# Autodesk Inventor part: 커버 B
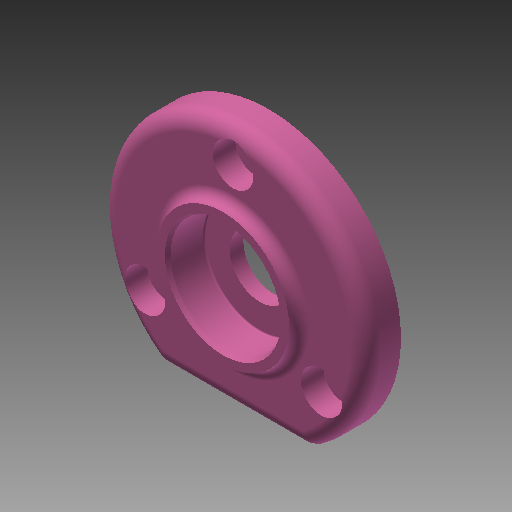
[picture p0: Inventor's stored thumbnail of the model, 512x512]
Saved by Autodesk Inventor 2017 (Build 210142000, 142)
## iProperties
Created: 2020-04
Part Number: 커버 B
Material: 알루미늄 6061
Document SubType Name: Modeling
Designer: mduedu
Density: 2.71 g/cm^3
Appearance: 분홍색
Mass: 33.6764 g
Surface Area: 62.2842 cm^2
Volume: 12.4267 cm^3
Author: mduedu
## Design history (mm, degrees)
sketch "스케치1"
  geometry: C1 r 26 at (0, 0); 1 further point
  constraints: 1 centre point, 1 coincident
  dimensions: "d0" = 52 diameter of C1
extrude "돌출1" new body sketch "스케치1" distance "d1" = 7; taper "d2" = 0 deg
sketch "스케치2"
  geometry: L1 (-14.62, -21.5)-(14.62, -21.5); A1 r 26 centre (0, 0) between (-14.62, -21.5) and (14.62, -21.5) reference; 1 further point
  constraints: 2 end point, 2 point on circle, 1 horizontal
  dimensions: "d3" = 21.5 distance from line of L1 point (0, 0)
extrude "돌출2" cut sketch "스케치2" stored distance "d4" = 7; taper "d5" = 0 deg
sketch "스케치6"
  geometry: C1 r 13 at (0, 0); 1 further point
  constraints: 1 centre point, 1 coincident
  dimensions: "d29" = 26 diameter of C1
extrude "돌출5" join sketch "스케치6" distance "d30" = 2; taper "d31" = 0 deg
fillet "모깎기1" dims "d6" = 3
fillet "모깎기2" dims "d7" = 3
fillet "모깎기4" dims "d33" = 2
sketch "스케치3" dims "d8" = 40
  geometry: 3 further points
  constraints: 2 vertical alignment, 1 coincident, 2 other
hole "구멍1" sketch "스케치3" at (0, 20) diameter "d9" = 4.5; stored, may be unused: countersink angle "d13" = 90 deg, drill point angle "d15" = 118 deg; dims "d10" = 6, "d11" = 8, "d12" = 4.4, "d14" = 8
sketch "스케치4"
  geometry: C1 r 14 at (0, 0); 1 further point
  constraints: 1 centre point, 1 coincident
  dimensions: "d19" = 28 diameter of C1
extrude "돌출3" join sketch "스케치4" distance "d20" = 4; taper "d21" = 0 deg
sketch "스케치5"
  geometry: C1 r 12 at (0, 0); 1 further point
  constraints: 1 centre point, 1 coincident
  dimensions: "d22" = 24 diameter of C1
extrude "돌출4" cut sketch "스케치5" distance "d23" = 3; taper "d24" = 0 deg
fillet "모깎기3" dims "d25" = 3
chamfer "모따기1" distance "d26" = 0.5; stored, may be unused: second distance "d27" = 2, angle "d28" = 45 deg
sketch "스케치7"
  geometry: 2 further points
  constraints: 1 coincident
hole "구멍2" sketch "스케치7" at (0, 0) diameter "d34" = 12; stored, may be unused: countersink angle "d38" = 90 deg, drill point angle "d40" = 118 deg; dims "d35" = 6, "d36" = 22, "d37" = 7.3, "d39" = 8
fillet "모깎기5" dims "d41" = 0.3
chamfer "모따기2" distance "d42" = 0.7; stored, may be unused: second distance "d43" = 2, angle "d44" = 30 deg
node "솔리드1"
pattern_circular "원형 패턴1" dims angle "d17" = 360 deg
node "투영된 루프1"
